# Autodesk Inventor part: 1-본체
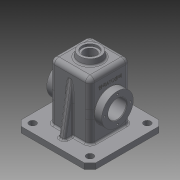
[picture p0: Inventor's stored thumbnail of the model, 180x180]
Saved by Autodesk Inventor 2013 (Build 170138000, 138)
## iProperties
Created: 2016-02
Part Number: 1-본체
Material: 일반
Document SubType Name: Modeling
Designer: max6
Density: 1 g/cm^3
Author: max6
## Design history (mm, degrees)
sketch "스케치1"
  geometry: L1 (-65, 65)-(65, 65); L2 (65, 65)-(65, -65); L3 (65, -65)-(-65, -65); L4 (-65, -65)-(-65, 65); 3 further points
  constraints: 8 end point, 2 midpoint, 2 parallel, 1 horizontal, 1 horizontal alignment, 1 perpendicular, 1 vertical alignment
  dimensions: "d0" = 130 distance between parallel lines of L2 L4; "d2" = 130 distance between parallel lines of L3 L1
extrude "돌출1" new body sketch "스케치1" distance "d3" = 10; taper "d4" = 0 deg
sketch "스케치2"
  geometry: L1 (-35, 35)-(35, 35); L2 (35, 35)-(35, -35); L3 (35, -35)-(-35, -35); L4 (-35, -35)-(-35, 35); 3 further points
  constraints: 8 end point, 2 midpoint, 2 parallel, 1 horizontal, 1 horizontal alignment, 1 perpendicular, 1 vertical alignment
  dimensions: "d5" = 70 distance between parallel lines of L2 L4; "d7" = 70 distance between parallel lines of L3 L1
extrude "돌출2" join sketch "스케치2" distance "d8" = 100; taper "d9" = 0 deg
feature "쉘1" dims "d14" = 10, "d15" = 5
sketch "스케치5"
  geometry: C1 r 20 at (0, 0); 1 further point
  constraints: 1 centre point, 1 coincident
  dimensions: "d17" = 40 diameter of C1
extrude "돌출4" join sketch "스케치5" distance "d19" = 10; taper "d20" = 0 deg
sketch "스케치6"
  geometry: L1 (-35, 10)-(-35, 110) reference; L2 (-30, 0)-(-30, 105) reference; L3 (-23, 55)-(-23, 75.5); L4 (-23, 75.5)-(-30, 82.5); L5 (-30, 82.5)-(-48, 82.5); L6 (-48, 82.5)-(-48, 55); L7 (-48, 55)-(-23, 55); L8 (-65, 0)-(65, 0) reference; 1 further point
  constraints: 10 end point, 2 perpendicular, 1 parallel, 1 point on line
  dimensions: "d21" = 55 diameter of L5 L7; "d23" = 13 distance between parallel lines of L1 L6; "d25" = 7 distance between parallel lines of L2 L3; "d26" = 135 deg angle of L2 L4; "d27" = 55 distance from line of L6.end L8
revolve "회전1" sketch "스케치6" stored, may be unused: angle "d28" = 90 deg
feature "면 기울기2" dims angle "d29" = 10 deg
sketch "스케치7"
  geometry: C1 r 18.237 at (0, 0) reference; 1 further point
  constraints: 1 coincident
hole "구멍1" sketch "스케치7" at (0, 0) diameter "d30" = 21; stored, may be unused: countersink angle "d34" = 90 deg, drill point angle "d36" = 118 deg; dims "d31" = 6, "d32" = 28, "d33" = 4, "d35" = 8
sketch "스케치8"
  geometry: C1 r 27.5 at (0, 0) reference; C2 r 16 at (0, 0); 1 further point
  constraints: 1 centre point, 1 coincident
  dimensions: "d37" = 32 diameter of C2
extrude "돌출5" cut sketch "스케치8" distance "d40" = 25; taper "d41" = 0 deg
sketch "스케치9"
  geometry: C1 r 16 at (0, 0) reference; 2 further points
  constraints: 1 vertical alignment
  dimensions: "d42" = 22.5 distance of point (0, 22.5) C1.centre
hole "구멍2" sketch "스케치9" at (0, 22.5) diameter "d43" = 3.242; stored, may be unused: countersink angle "d47" = 90 deg, drill point angle "d49" = 118 deg; dims "d44" = 8, "d45" = 28, "d46" = 4, "d48" = 10
sketch "스케치10"
  geometry: L1 (35, 10)-(35, 110) reference; L2 (65, 10)-(-65, 10) reference; L3 (35, 95.069)-(50, 10); L4 (65, 0)-(65, 10) reference; 1 further point
  constraints: 2 end point, 2 point on line
  dimensions: "d53" = 15 distance from line of L3.end L4; "d54" = 10 deg angle of L3 L4
extrude "돌출6" join sketch "스케치10" stored distance "d55" = 10; taper "d56" = 0 deg
fillet "모깎기2" dims "d58" = 3
fillet "모깎기3" dims "d59" = 0.5
fillet "모깎기4" dims "d60" = 8
fillet "모깎기5" dims "d61" = 8
fillet "모깎기7" dims "d63" = 3
fillet "모깎기8" dims "d64" = 3
chamfer "모따기1" distance "d65" = 10; stored, may be unused: second distance "d66" = 2, angle "d67" = 45 deg
fillet "모깎기9" dims "d70" = 3
fillet "모깎기10" dims "d71" = 3
chamfer "모따기2" distance "d72" = 1; stored, may be unused: second distance "d73" = 2, angle "d74" = 45 deg
sketch "스케치13"
  geometry: C1 r 6 at (50, 50); 1 further point
  constraints: 1 centre point
  dimensions: "d75" = 50 horizontal distance of C1.centre point (0, 0); "d76" = 50 horizontal distance of point (0, 0) C1.centre; "d78" = 12 diameter of C1
extrude "돌출7" cut sketch "스케치13" distance "d79" = 10; taper "d80" = 0 deg
sketch "스케치14"
  geometry: L1 (-65, 18.237)-(-65, -18.237) reference; L2 (-7.416, 35)-(-47, 35) reference; 2 further points
  constraints: 1 other
  dimensions: "d87" = 30 distance from line of L1 point (-35, 0); "d88" = 35 distance from line of L2 point (-35, 0)
feature "엠보싱1" sketch "스케치14" dims "d0" = 130, "d2" = 130, "d17" = 40, "d89" = 0.5, "d90" = 0
fillet "모깎기11" dims "d91" = 0.5
node "솔리드1"
pattern_circular "원형 패턴1" dims angle "d51" = 360 deg
mirror "대칭2"
mirror "대칭4"
pattern_linear "직사각형 패턴1" dims "d83" = 100
